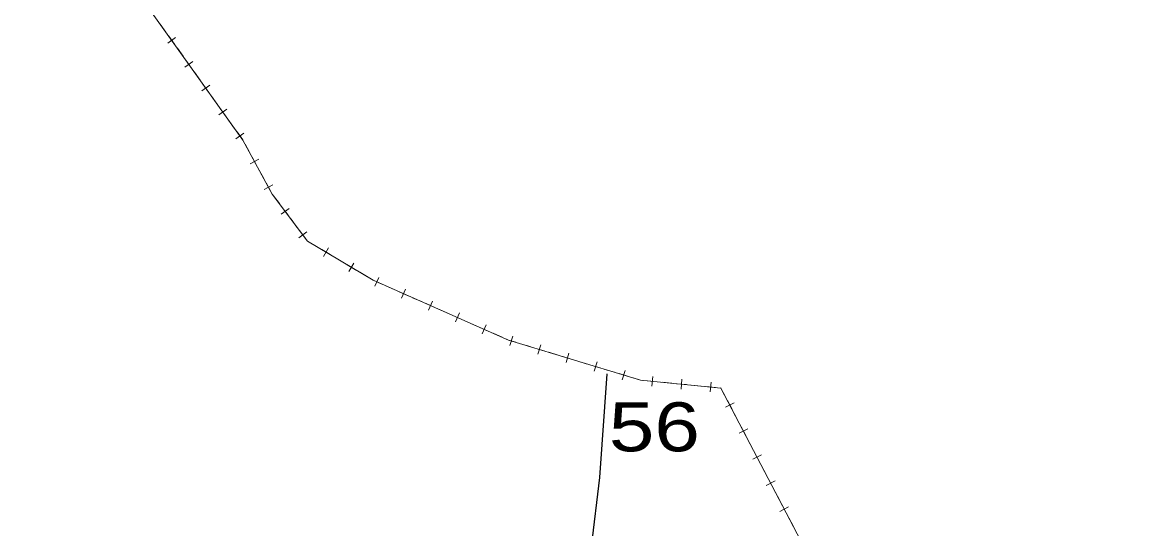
# Model space of a CAD drawing. Extents: x 476989 to 498418, y 4381813 to 4416555.
# Drawn here: x 486521 to 487660, y 4387996 to 4388513 of the extents above; entities that cross this region are included whole.
import ezdxf
from ezdxf.enums import TextEntityAlignment as Align

# ---------------------------------------------------------------- set-up
doc = ezdxf.new("R2010")
doc.units = 0
doc.header["$LTSCALE"] = 20
doc.layers.add('34', color=7, linetype='Continuous', lineweight=13)
doc.layers.add('6', color=7, linetype='Continuous', lineweight=25)

msp = doc.modelspace()

# ---------------------------------------------------------------- linework, layer by layer
at = {"layer": '34'}
for p, q in [((486661.73, 4388511.22), (486667.54, 4388503.08)), ((486677.41, 4388497.85), (486669.26, 4388492.04)), ((486670.43, 4388499.02), (486676.24, 4388490.88)), ((486679.14, 4388486.8), (486684.94, 4388478.66)), ((486694.81, 4388473.43), (486686.67, 4388467.62)), ((486687.84, 4388474.6), (486693.64, 4388466.45)), ((486696.55, 4388462.38), (486702.35, 4388454.24)), ((486712.22, 4388449.01), (486704.08, 4388443.2)), ((486705.25, 4388450.18), (486711.05, 4388442.03)), ((486713.95, 4388437.96), (486719.76, 4388429.82)), ((486729.63, 4388424.58), (486721.48, 4388418.78)), ((486722.65, 4388425.75), (486728.46, 4388417.61)), ((486731.36, 4388413.54), (486737.16, 4388405.4)), ((486747.03, 4388400.16), (486738.89, 4388394.36)), ((486740.06, 4388401.33), (486745.86, 4388393.19)), ((486748.28, 4388388.81), (486753.07, 4388380.04)), ((486755.46, 4388375.66), (486760.25, 4388366.88)), ((486762.24, 4388373.66), (486753.47, 4388368.87)), ((486762.64, 4388362.49), (486767.43, 4388353.71)), ((486776.61, 4388347.33), (486767.83, 4388342.54)), ((486769.82, 4388349.33), (486774.61, 4388340.55)), ((486777.26, 4388336.32), (486783.26, 4388328.32)), ((486793.25, 4388323.33), (486785.25, 4388317.33)), ((486786.25, 4388324.33), (486792.25, 4388316.33)), ((486795.25, 4388312.33), (486801.25, 4388304.33)), ((486811.25, 4388299.34), (486803.25, 4388293.34)), ((486804.25, 4388300.34), (486810.25, 4388292.34)), ((486813.78, 4388288.94), (486822.37, 4388283.81)), ((486826.65, 4388281.25), (486835.24, 4388276.12)), ((486833.51, 4388282.98), (486828.38, 4388274.39)), ((486839.53, 4388273.56), (486848.12, 4388268.44)), ((486852.4, 4388265.88), (486860.99, 4388260.75)), ((486859.26, 4388267.61), (486854.13, 4388259.02)), ((486865.28, 4388258.19), (486873.87, 4388253.06)), ((486884.69, 4388252.95), (486880.65, 4388243.8)), ((486891.82, 4388244.33), (486900.97, 4388240.29)), ((486912.12, 4388240.83), (486908.08, 4388231.68)), ((486905.53, 4388238.27), (486914.68, 4388234.23)), ((486919.25, 4388232.21), (486928.39, 4388228.17)), ((486939.55, 4388228.7), (486935.51, 4388219.55)), ((486932.96, 4388226.15), (486942.11, 4388222.11)), ((486946.68, 4388220.08), (486955.82, 4388216.04)), ((486966.98, 4388216.58), (486962.94, 4388207.43)), ((486960.39, 4388214.02), (486969.53, 4388209.98)), ((486974.11, 4388207.96), (486983.25, 4388203.92)), ((486994.41, 4388204.45), (486990.37, 4388195.3)), ((486987.82, 4388201.9), (486996.96, 4388197.86)), ((487001.54, 4388195.83), (487010.68, 4388191.79)), ((487021.4, 4388192.89), (487018.5, 4388183.32)), ((487029.52, 4388185.2), (487039.09, 4388182.29)), ((487050.1, 4388184.17), (487047.19, 4388174.6)), ((487043.86, 4388180.84), (487053.43, 4388177.94)), ((487058.22, 4388176.48), (487067.78, 4388173.58)), ((487072.56, 4388172.13), (487082.13, 4388169.22)), ((487078.8, 4388175.46), (487075.89, 4388165.89)), ((487086.91, 4388167.77), (487096.48, 4388164.86)), ((487101.25, 4388163.41), (487110.82, 4388160.51)), ((487107.49, 4388166.74), (487104.59, 4388157.17)), ((487115.61, 4388159.05), (487125.18, 4388156.15)), ((487129.95, 4388154.7), (487139.52, 4388151.79)), ((487136.19, 4388158.03), (487133.28, 4388148.46)), ((487158.91, 4388147.33), (487168.87, 4388146.35)), ((487164.38, 4388151.82), (487163.4, 4388141.86)), ((487194.22, 4388148.9), (487193.25, 4388138.95)), ((487173.84, 4388145.87), (487183.8, 4388144.9)), ((487188.76, 4388144.41), (487198.71, 4388143.44)), ((487203.69, 4388142.96), (487213.64, 4388141.99)), ((487218.61, 4388141.5), (487228.56, 4388140.53)), ((487224.07, 4388145.99), (487223.1, 4388136.04)), ((487247.48, 4388125.01), (487238.62, 4388120.38)), ((487240.73, 4388127.13), (487245.36, 4388118.26)), ((487247.68, 4388113.83), (487252.31, 4388104.97)), ((487261.37, 4388098.44), (487252.51, 4388093.8)), ((487254.63, 4388100.55), (487259.26, 4388091.69)), ((487261.58, 4388087.26), (487266.21, 4388078.39)), ((487275.27, 4388071.86), (487266.41, 4388067.23)), ((487268.52, 4388073.97), (487273.15, 4388065.11)), ((487275.47, 4388060.68), (487280.1, 4388051.82)), ((487289.16, 4388045.28), (487280.3, 4388040.65)), ((487282.42, 4388047.4), (487287.05, 4388038.53)), ((487289.37, 4388034.1), (487294, 4388025.24)), ((487303.06, 4388018.7), (487294.2, 4388014.07)), ((487296.31, 4388020.82), (487300.94, 4388011.96)), ((487303.26, 4388007.53), (487307.89, 4387998.66))]:
    msp.add_line(p, q, dxfattribs=at)
for points in [[(486520.9, 4388755.72), (486603, 4388633), (486612, 4388581), (486746, 4388393), (486776, 4388338), (486812, 4388290), (486879, 4388250), (487017, 4388189), (487152, 4388148), (487234, 4388140), (487360, 4387899), (487497, 4387717), (487531, 4387660), (487608, 4387440), (487634, 4387181), (487675, 4387065), (487547, 4387001), (487350, 4386921), (487175, 4386900), (487110, 4386912), (487380, 4386493), (487280.6, 4386441.97)], [(486878.15, 4388250.5), (486879, 4388250), (486887.25, 4388246.36)], [(487015.25, 4388189.77), (487017, 4388189), (487024.74, 4388186.65)], [(487144.3, 4388150.34), (487152, 4388148), (487153.95, 4388147.81)], [(487233.54, 4388140.04), (487234, 4388140), (487238.42, 4388131.55)]]:
    msp.add_lwpolyline(points, dxfattribs=at)
at = {"layer": '6'}
msp.add_lwpolyline([(486963.22, 4387547.94), (486934.94, 4387619.76), (486914.2, 4387682.13), (486891.58, 4387725.6), (486891.58, 4387736.94), (486938.71, 4387776.63), (487048.06, 4387863.56), (487093.3, 4387907.03), (487110.27, 4388048.78), (487117.81, 4388154.62)], dxfattribs=at)

# ---------------------------------------------------------------- texts
at = {"layer": '6', "width": 1.25}
msp.add_text('56', height=50, dxfattribs=at).set_placement((487166.02, 4388075.39), align=Align.CENTER)

doc.saveas('drawing.dxf')
